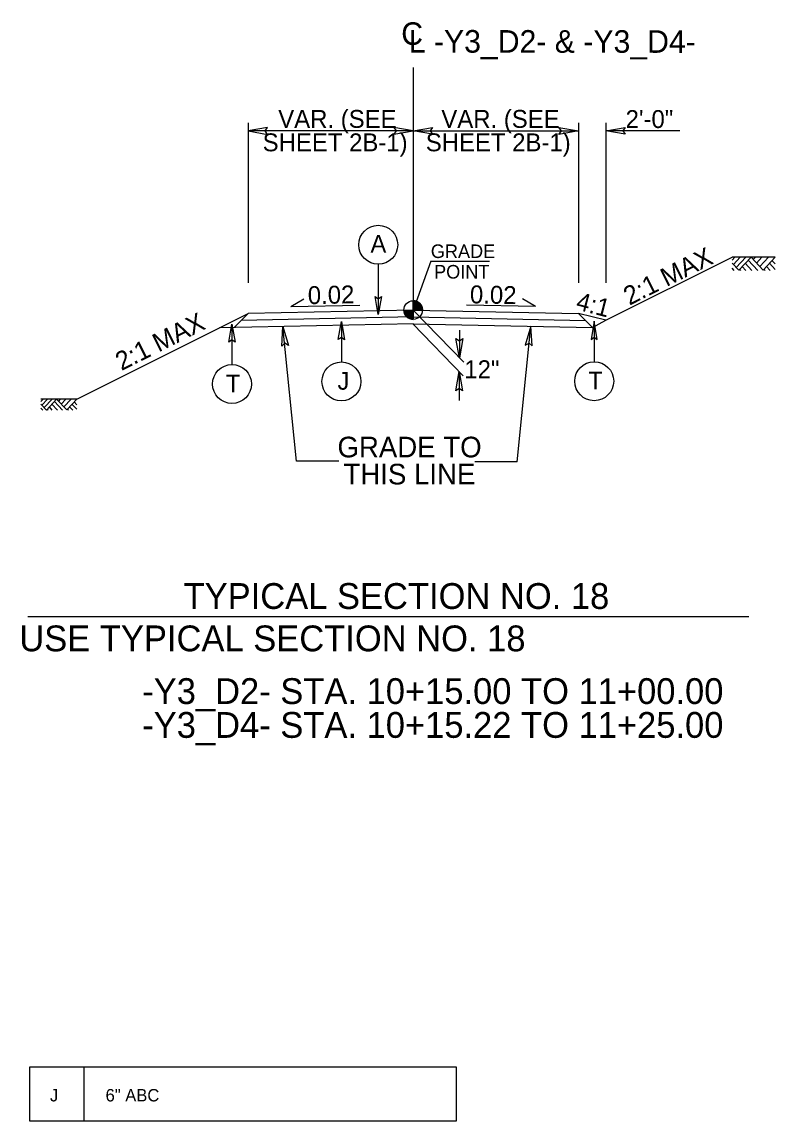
# Model space of a CAD drawing. Extents: x 1901670 to 1902225, y 193498 to 194278.
# Drawn here: x 1902144.6 to 1902199.3, y 193525 to 193604.8 of the extents above; entities that cross this region are included whole.
import ezdxf

# ---------------------------------------------------------------- set-up
doc = ezdxf.new("R2010")
doc.units = 0
for name, color, linetype in [('Old_Level_1', 7, 'Continuous'), ('Old_Level_11', 7, 'Continuous'), ('Old_Level_20', 7, 'Continuous'), ('Old_Level_3', 7, 'Continuous'), ('Prop Dimension Text', 7, 'Continuous'), ('Prop Lane Arrow CELL', 7, 'Continuous'), ('Prop Pavement Schedule Description CELL', 7, 'Continuous'), ('Typical Arrow Superelevation CELL', 7, 'Continuous'), ('Typical Hinge Slope Arterial CELL', 7, 'Continuous'), ('Typical Hinge Slope Interstate CELL', 7, 'Continuous'), ('Typical Terminator CELL', 7, 'Continuous'), ('Typical Text Centerline CELL', 7, 'Continuous')]:
    doc.layers.add(name, color=color, linetype=linetype)

# ---------------------------------------------------------------- blocks, each defined once
blk = doc.blocks.new('TERMINATOR')
at = {"layer": 'Typical Terminator CELL'}
blk.add_lwpolyline([(-0.469, 0.081), (0, 0), (-0.471, -0.083), (-0.411, 0)], close=True, dxfattribs=at)

msp = doc.modelspace()

# ---------------------------------------------------------------- linework, layer by layer
at = {"layer": 'Old_Level_1'}
for p, q in [((1902172.995, 193583.867), (1902172.995, 193584.542)), ((1902172.32, 193583.867), (1902172.995, 193583.867)), ((1902172.993, 193583.192), (1902172.995, 193583.867)), ((1902172.995, 193583.867), (1902172.993, 193583.192)), ((1902173.67, 193583.867), (1902172.995, 193583.867)), ((1902172.995, 193583.867), (1902176.669, 193580.071)), ((1902172.975, 193582.867), (1902176.631, 193579.09)), ((1902176.353, 193582.397), (1902176.353, 193580.397)), ((1902176.33, 193579.401), (1902176.33, 193577.306)), ((1902146.112, 193577.4), (1902145.942, 193577.217)), ((1902146.432, 193577.4), (1902146.018, 193576.956)), ((1902146.765, 193577.4), (1902146.185, 193576.777)), ((1902147.087, 193577.399), (1902146.346, 193576.603)), ((1902147.818, 193576.613), (1902147.087, 193577.399)), ((1902147.351, 193577.4), (1902147.218, 193577.257)), ((1902147.753, 193577.4), (1902147.42, 193577.041)), ((1902148.151, 193577.4), (1902147.618, 193576.827)), ((1902148.542, 193577.392), (1902147.818, 193576.613)), ((1902146.346, 193576.603), (1902145.942, 193577.038)), ((1902146.076, 193576.595), (1902145.942, 193576.738)), ((1902146.477, 193576.595), (1902146.408, 193576.669)), ((1902146.772, 193576.595), (1902146.555, 193576.828)), ((1902147.138, 193576.595), (1902146.738, 193577.024)), ((1902147.508, 193576.595), (1902146.922, 193577.223)), ((1902147.943, 193576.595), (1902147.872, 193576.671)), ((1902148.254, 193576.595), (1902148.027, 193576.838)), ((1902148.542, 193576.658), (1902148.2, 193577.024)), ((1902148.542, 193576.991), (1902148.356, 193577.191)), ((1902144.993, 193561.614), (1902197.386, 193561.614))]:
    msp.add_line(p, q, dxfattribs=at)
for points in [[(1902173.001, 193584.542), (1902173.001, 193584.542), (1902173.001, 193583.867)], [(1902173.014, 193584.542), (1902173.014, 193583.867)], [(1902173.028, 193584.54), (1902173.028, 193583.867)], [(1902173.041, 193584.54), (1902173.041, 193583.867)], [(1902173.055, 193584.539), (1902173.055, 193583.867)], [(1902173.068, 193584.537), (1902173.068, 193583.867)], [(1902173.082, 193584.536), (1902173.082, 193583.867)], [(1902173.095, 193584.534), (1902173.095, 193583.867)], [(1902173.109, 193584.533), (1902173.109, 193583.867)], [(1902173.122, 193584.53), (1902173.122, 193583.867)], [(1902173.136, 193584.527), (1902173.136, 193583.867)], [(1902173.149, 193584.524), (1902173.149, 193583.867)], [(1902173.163, 193584.521), (1902173.163, 193583.867)], [(1902173.176, 193584.516), (1902173.176, 193583.867)], [(1902173.19, 193584.513), (1902173.19, 193583.867)], [(1902173.203, 193584.509), (1902173.203, 193583.867)], [(1902173.217, 193584.504), (1902173.217, 193583.867)], [(1902173.23, 193584.5), (1902173.23, 193583.867)], [(1902173.244, 193584.494), (1902173.244, 193583.867)], [(1902173.257, 193584.488), (1902173.257, 193583.867)], [(1902173.271, 193584.482), (1902173.271, 193583.867)], [(1902173.284, 193584.476), (1902173.284, 193583.867)], [(1902173.298, 193584.47), (1902173.298, 193583.867)], [(1902173.311, 193584.462), (1902173.311, 193583.867)], [(1902173.325, 193584.455), (1902173.325, 193583.867)], [(1902173.338, 193584.447), (1902173.338, 193583.867)], [(1902173.352, 193584.44), (1902173.352, 193583.867)], [(1902172.323, 193583.867), (1902172.323, 193583.793)], [(1902172.336, 193583.867), (1902172.336, 193583.714)], [(1902172.35, 193583.867), (1902172.35, 193583.666)], [(1902172.363, 193583.867), (1902172.363, 193583.625)], [(1902172.377, 193583.867), (1902172.377, 193583.594)], [(1902172.39, 193583.867), (1902172.39, 193583.565)], [(1902172.404, 193583.867), (1902172.404, 193583.54)], [(1902172.417, 193583.867), (1902172.417, 193583.516)], [(1902172.431, 193583.867), (1902172.431, 193583.495)], [(1902172.444, 193583.867), (1902172.444, 193583.475)], [(1902172.458, 193583.867), (1902172.458, 193583.457)], [(1902172.471, 193583.867), (1902172.471, 193583.441)], [(1902172.485, 193583.867), (1902172.485, 193583.424)], [(1902172.498, 193583.867), (1902172.498, 193583.409)], [(1902172.512, 193583.867), (1902172.512, 193583.394)], [(1902172.525, 193583.867), (1902172.525, 193583.381)], [(1902172.539, 193583.867), (1902172.539, 193583.369)], [(1902172.552, 193583.867), (1902172.552, 193583.357)], [(1902172.566, 193583.867), (1902172.566, 193583.345)], [(1902172.579, 193583.867), (1902172.579, 193583.334)], [(1902172.593, 193583.867), (1902172.593, 193583.324)], [(1902172.606, 193583.867), (1902172.606, 193583.315)], [(1902172.62, 193583.867), (1902172.62, 193583.306)], [(1902172.633, 193583.867), (1902172.633, 193583.297)], [(1902172.647, 193583.867), (1902172.647, 193583.288)], [(1902172.66, 193583.867), (1902172.66, 193583.28)], [(1902172.674, 193583.867), (1902172.674, 193583.273)], [(1902172.687, 193583.867), (1902172.687, 193583.265)], [(1902172.701, 193583.867), (1902172.701, 193583.259)], [(1902172.714, 193583.867), (1902172.714, 193583.253)], [(1902172.728, 193583.867), (1902172.728, 193583.247)], [(1902172.741, 193583.867), (1902172.741, 193583.241)], [(1902172.755, 193583.867), (1902172.755, 193583.235)], [(1902172.768, 193583.867), (1902172.768, 193583.231)], [(1902172.782, 193583.867), (1902172.782, 193583.226)], [(1902172.795, 193583.867), (1902172.795, 193583.222)], [(1902172.809, 193583.867), (1902172.809, 193583.219)], [(1902172.822, 193583.867), (1902172.822, 193583.214)], [(1902172.836, 193583.867), (1902172.836, 193583.211)], [(1902172.849, 193583.867), (1902172.849, 193583.208)], [(1902172.863, 193583.867), (1902172.863, 193583.205)], [(1902172.876, 193583.867), (1902172.876, 193583.202)], [(1902172.89, 193583.867), (1902172.89, 193583.201)], [(1902172.903, 193583.867), (1902172.903, 193583.198)], [(1902172.917, 193583.867), (1902172.917, 193583.196)], [(1902172.93, 193583.867), (1902172.93, 193583.195)], [(1902172.944, 193583.867), (1902172.944, 193583.193)], [(1902172.957, 193583.867), (1902172.957, 193583.193)], [(1902172.971, 193583.867), (1902172.971, 193583.192)], [(1902172.984, 193583.867), (1902172.984, 193583.192), (1902172.984, 193583.192)], [(1902173.365, 193584.431), (1902173.365, 193583.867)], [(1902173.379, 193584.422), (1902173.379, 193583.867)], [(1902173.392, 193584.411), (1902173.392, 193583.867)], [(1902173.406, 193584.402), (1902173.406, 193583.867)], [(1902173.419, 193584.392), (1902173.419, 193583.867)], [(1902173.433, 193584.38), (1902173.433, 193583.867)], [(1902173.446, 193584.368), (1902173.446, 193583.867)], [(1902173.46, 193584.356), (1902173.46, 193583.867)], [(1902173.473, 193584.342), (1902173.473, 193583.867)], [(1902173.487, 193584.329), (1902173.487, 193583.867)], [(1902173.5, 193584.314), (1902173.5, 193583.867)], [(1902173.514, 193584.297), (1902173.514, 193583.867)], [(1902173.527, 193584.281), (1902173.527, 193583.867)], [(1902173.541, 193584.263), (1902173.541, 193583.867)], [(1902173.554, 193584.243), (1902173.554, 193583.867)], [(1902173.568, 193584.222), (1902173.568, 193583.867)], [(1902173.581, 193584.2), (1902173.581, 193583.867)], [(1902173.595, 193584.176), (1902173.595, 193583.867)], [(1902173.608, 193584.147), (1902173.608, 193583.867)], [(1902173.622, 193584.116), (1902173.622, 193583.867)], [(1902173.635, 193584.078), (1902173.635, 193583.867)], [(1902173.649, 193584.032), (1902173.649, 193583.867)], [(1902173.662, 193583.963), (1902173.662, 193583.867)], [(1902148.542, 193577.4), (1902145.942, 193577.4)]]:
    msp.add_lwpolyline(points, dxfattribs=at)
msp.add_circle((1902172.994, 193583.867), 0.675, dxfattribs=at)
for start, end in [(359.99048, 89.99048), (179.99048, 269.99048)]:
    msp.add_arc((1902172.994, 193583.867), 0.675, start, end, dxfattribs=at)
at = {"layer": 'Old_Level_11'}
for p, q in [((1902170.455, 193587.192), (1902170.455, 193583.538)), ((1902167.779, 193583.028), (1902167.779, 193580.094)), ((1902186.148, 193583.047), (1902186.148, 193580.112)), ((1902159.824, 193582.841), (1902159.824, 193579.907))]:
    msp.add_line(p, q, dxfattribs=at)
for points in [[(1902170.68, 193584.847), (1902170.455, 193583.538), (1902170.222, 193584.854), (1902170.455, 193584.687)], [(1902167.554, 193581.719), (1902167.779, 193583.028), (1902168.012, 193581.712), (1902167.779, 193581.879)], [(1902186.373, 193581.737), (1902186.148, 193583.047), (1902185.915, 193581.73), (1902186.148, 193581.898)], [(1902159.599, 193581.532), (1902159.824, 193582.841), (1902160.057, 193581.525), (1902159.824, 193581.692)]]:
    msp.add_lwpolyline(points, close=True, dxfattribs=at)
for centre in [(1902170.455, 193588.606), (1902159.824, 193578.493), (1902167.779, 193578.68), (1902186.148, 193578.698)]:
    msp.add_circle(centre, 1.414, dxfattribs=at)
at = {"layer": 'Old_Level_3'}
for q in [(1902172.995, 193583.867), (1902178.541, 193587.409)]:
    msp.add_line((1902174.284, 193587.409), q, dxfattribs=at)
at = {"layer": 'Prop Lane Arrow CELL'}
for p, q in [((1902160.995, 193597.472), (1902160.995, 193585.847)), ((1902184.995, 193597.472), (1902184.995, 193585.847)), ((1902186.995, 193597.472), (1902186.995, 193585.847)), ((1902172.995, 193596.872), (1902160.995, 193596.872)), ((1902172.995, 193596.872), (1902184.995, 193596.872)), ((1902192.365, 193596.872), (1902186.995, 193596.872)), ((1902196.371, 193587.713), (1902196.167, 193587.493)), ((1902196.755, 193587.713), (1902196.258, 193587.18)), ((1902197.154, 193587.713), (1902196.458, 193586.965)), ((1902197.541, 193587.712), (1902196.652, 193586.756)), ((1902198.418, 193586.768), (1902197.541, 193587.712)), ((1902197.858, 193587.713), (1902197.698, 193587.541)), ((1902198.34, 193587.713), (1902197.94, 193587.282)), ((1902198.817, 193587.713), (1902198.178, 193587.025)), ((1902199.287, 193587.703), (1902198.418, 193586.768)), ((1902196.652, 193586.756), (1902196.167, 193587.278)), ((1902196.328, 193586.747), (1902196.167, 193586.918)), ((1902196.809, 193586.747), (1902196.726, 193586.836)), ((1902197.163, 193586.747), (1902196.902, 193587.026)), ((1902197.602, 193586.747), (1902197.122, 193587.262)), ((1902198.046, 193586.747), (1902197.343, 193587.5)), ((1902198.568, 193586.747), (1902198.483, 193586.838)), ((1902198.941, 193586.747), (1902198.669, 193587.038)), ((1902199.287, 193586.822), (1902198.876, 193587.261)), ((1902199.287, 193587.222), (1902199.064, 193587.462)), ((1902172.995, 193583.867), (1902160.995, 193583.627)), ((1902172.995, 193583.867), (1902184.995, 193583.627)), ((1902173.015, 193582.867), (1902158.911, 193582.585)), ((1902159.974, 193582.606), (1902160.995, 193583.627)), ((1902173.005, 193583.367), (1902160.484, 193583.116)), ((1902172.975, 193582.867), (1902186.015, 193582.606)), ((1902172.985, 193583.367), (1902185.505, 193583.116)), ((1902186.015, 193582.606), (1902184.995, 193583.627)), ((1902186.015, 193582.606), (1902186.995, 193583.127)), ((1902164.522, 193572.887), (1902163.532, 193582.677)), ((1902180.547, 193572.838), (1902181.545, 193582.695)), ((1902167.601, 193572.887), (1902164.522, 193572.887)), ((1902180.547, 193572.838), (1902177.468, 193572.838))]:
    msp.add_line(p, q, dxfattribs=at)
msp.add_lwpolyline([(1902199.287, 193587.713), (1902196.167, 193587.713)], dxfattribs=at)
at = {"layer": 'Prop Pavement Schedule Description CELL'}
msp.add_lwpolyline([(1902149.089, 193524.964), (1902145.142, 193524.964), (1902145.142, 193528.91), (1902176.115, 193528.91), (1902176.115, 193524.964), (1902149.089, 193524.964), (1902149.089, 193528.91)], dxfattribs=at)
at = {"layer": 'Typical Arrow Superelevation CELL'}
for p, q in [((1902164.113, 193584.118), (1902165.052, 193584.686)), ((1902181.877, 193584.118), (1902180.937, 193584.686)), ((1902164.113, 193584.118), (1902169.124, 193584.218)), ((1902181.877, 193584.118), (1902176.866, 193584.218))]:
    msp.add_line(p, q, dxfattribs=at)
at = {"layer": 'Typical Hinge Slope Arterial CELL'}
for p, q in [((1902186.995, 193583.127), (1902196.167, 193587.713)), ((1902148.542, 193577.4), (1902160.995, 193583.627))]:
    msp.add_line(p, q, dxfattribs=at)
at = {"layer": 'Typical Hinge Slope Interstate CELL'}
msp.add_line((1902186.995, 193583.127), (1902184.995, 193583.627), dxfattribs=at)
at = {"layer": 'Typical Terminator CELL'}
for points in [[(1902162.401, 193597.115), (1902160.995, 193596.872), (1902162.408, 193596.623), (1902162.229, 193596.872)], [(1902171.589, 193596.63), (1902172.995, 193596.872), (1902171.581, 193597.122), (1902171.76, 193596.872)], [(1902174.401, 193596.63), (1902172.995, 193596.872), (1902174.408, 193597.122), (1902174.229, 193596.872)], [(1902183.589, 193597.115), (1902184.995, 193596.872), (1902183.581, 193596.623), (1902183.76, 193596.872)], [(1902188.401, 193596.63), (1902186.995, 193596.872), (1902188.408, 193597.122), (1902188.229, 193596.872)], [(1902163.445, 193581.253), (1902163.532, 193582.677), (1902163.935, 193581.299), (1902163.667, 193581.45)], [(1902181.631, 193581.271), (1902181.545, 193582.695), (1902181.141, 193581.317), (1902181.41, 193581.469)]]:
    msp.add_lwpolyline(points, close=True, dxfattribs=at)
at = {"layer": 'Typical Text Centerline CELL'}
msp.add_line((1902172.995, 193601.473), (1902172.995, 193583.867), dxfattribs=at)

# ---------------------------------------------------------------- block references
at = {"layer": 'Old_Level_1', "xscale": 3, "yscale": 3}
for p, rotation in [((1902176.353, 193580.397), -90), ((1902176.33, 193579.401), 90)]:
    msp.add_blockref('TERMINATOR', p, dxfattribs=dict(at, rotation=rotation))

# ---------------------------------------------------------------- texts
at = {"layer": 'Old_Level_1'}
msp.add_text('2\'-0"', height=1.3, dxfattribs=at).set_placement((1902188.431, 193597.087))
at = {"layer": 'Old_Level_11'}
for s, p in [('GRADE', (1902174.275, 193587.646)), ('POINT', (1902174.512, 193586.155))]:
    msp.add_text(s, height=0.984, dxfattribs=at).set_placement(p)
at = {"layer": 'Old_Level_20'}
for s, height, p in [('A', 1.279, (1902169.896, 193588.045)), ('12"', 1.3, (1902176.711, 193578.917)), ('T', 1.279, (1902159.388, 193577.896)), ('J', 1.279, (1902167.497, 193578.082)), ('T', 1.279, (1902185.719, 193578.101))]:
    msp.add_text(s, height=height, dxfattribs=at).set_placement(p)
at = {"layer": 'Prop Dimension Text'}
for rotation, p in [(1.1462, (1902165.349, 193584.291)), (358.8538, (1902177.108, 193584.361))]:
    msp.add_text('0.02', height=1.3, rotation=rotation, dxfattribs=at).set_placement(p)
at = {"layer": 'Prop Lane Arrow CELL'}
for s, height, p in [('VAR. (SEE', 1.3, (1902163.188, 193597.101)), ('VAR. (SEE', 1.3, (1902175.039, 193597.101)), ('SHEET 2B-1)', 1.3, (1902162.058, 193595.397)), ('SHEET 2B-1)', 1.3, (1902173.909, 193595.397)), ('TYPICAL SECTION NO. 18', 1.875, (1902156.31, 193562.158)), ('USE TYPICAL SECTION NO. 18', 1.875, (1902144.373, 193559.08)), ('-Y3_D2- STA. 10+15.00 TO 11+00.00', 1.875, (1902153.305, 193555.253)), ('-Y3_D4- STA. 10+15.22 TO 11+25.00', 1.875, (1902153.305, 193552.795))]:
    msp.add_text(s, height=height, dxfattribs=at).set_placement(p)
for s, p in [('GRADE TO', (1902167.492, 193573.166)), ('THIS LINE', (1902167.928, 193571.199))]:
    msp.add_text(s, height=1.5, rotation=0.00016, dxfattribs=at).set_placement(p)
at = {"layer": 'Prop Pavement Schedule Description CELL'}
for s, p in [('J', (1902146.601, 193526.387)), ('    6" ABC', (1902149.304, 193526.387))]:
    msp.add_text(s, height=0.9, dxfattribs=at).set_placement(p)
at = {"layer": 'Typical Hinge Slope Arterial CELL'}
for p in [(1902188.709, 193584.183), (1902151.795, 193579.432)]:
    msp.add_text('2:1 MAX', height=1.35, rotation=26.56505, dxfattribs=at).set_placement(p)
at = {"layer": 'Typical Hinge Slope Interstate CELL'}
msp.add_text('4:1', height=1.3, rotation=345.52839, dxfattribs=at).set_placement((1902184.754, 193583.93))
at = {"layer": 'Typical Text Centerline CELL'}
msp.add_text('C', height=1.64, dxfattribs=at).set_placement((1902172.126, 193603.125))
msp.add_text('L -Y3_D2- & -Y3_D4-', height=1.64109, rotation=359.9469, dxfattribs=at).set_placement((1902172.672, 193602.565))

doc.saveas('drawing.dxf')
